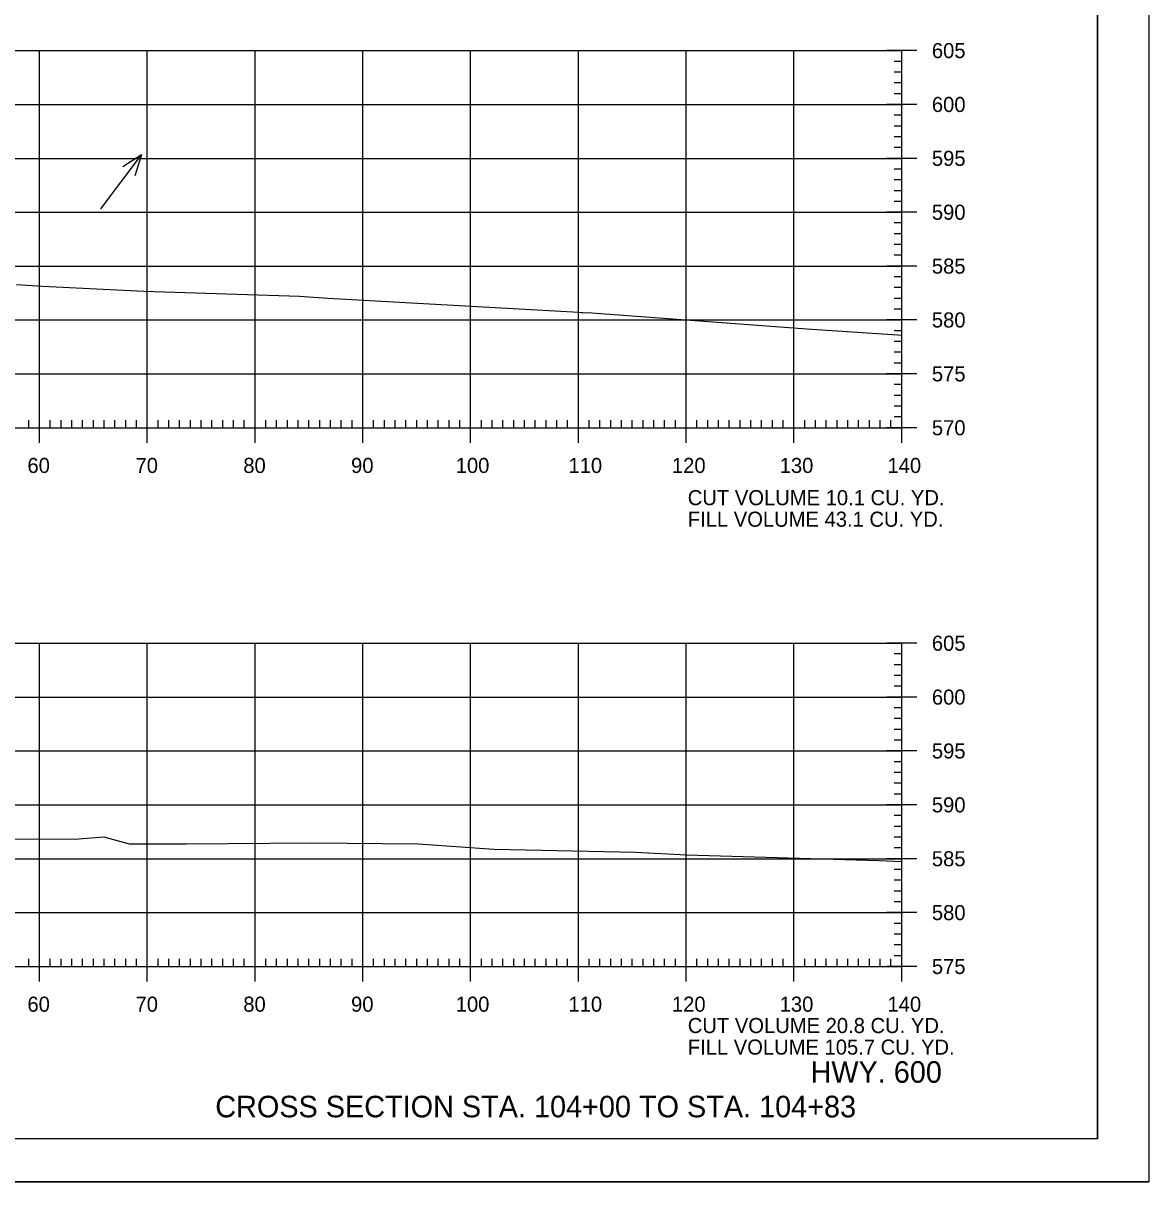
# Model space of a CAD drawing. Extents: x 961436 to 1372525, y 380079 to 2027791.
# Drawn here: x 1371253.4 to 1371357.8, y 380322.4 to 380429.9 of the extents above; entities that cross this region are included whole.
import ezdxf

# ---------------------------------------------------------------- set-up
doc = ezdxf.new("R2010")
doc.units = 0
for name, color, linetype in [('R_Axis', 7, 'Continuous'), ('R_Axis Annot', 7, 'Continuous'), ('R_Border', 7, 'Continuous'), ('R_Draft', 7, 'Continuous'), ('R_Exist Surface', 7, 'Continuous'), ('R_Grid', 7, 'Continuous'), ('R_No Plot', 7, 'Continuous'), ('R_Water Annot', 7, 'Continuous')]:
    doc.layers.add(name, color=color, linetype=linetype)

msp = doc.modelspace()

# ---------------------------------------------------------------- linework, layer by layer
at = {"layer": 'R_Axis'}
for p, q in [((1371336.28, 380427.4), (1371333.48, 380427.4)), ((1371334.88, 380392.4), (1371334.88, 380427.4)), ((1371334.88, 380426.4), (1371334.18, 380426.4)), ((1371334.88, 380425.4), (1371334.18, 380425.4)), ((1371334.88, 380424.4), (1371334.18, 380424.4)), ((1371334.88, 380423.4), (1371334.18, 380423.4)), ((1371336.28, 380422.4), (1371333.48, 380422.4)), ((1371334.88, 380421.4), (1371334.18, 380421.4)), ((1371334.88, 380420.4), (1371334.18, 380420.4)), ((1371334.88, 380419.4), (1371334.18, 380419.4)), ((1371334.88, 380418.4), (1371334.18, 380418.4)), ((1371336.28, 380417.4), (1371333.48, 380417.4)), ((1371334.88, 380416.4), (1371334.18, 380416.4)), ((1371334.88, 380415.4), (1371334.18, 380415.4)), ((1371334.88, 380414.4), (1371334.18, 380414.4)), ((1371334.88, 380413.4), (1371334.18, 380413.4)), ((1371336.28, 380412.4), (1371333.48, 380412.4)), ((1371334.88, 380411.4), (1371334.18, 380411.4)), ((1371334.88, 380410.4), (1371334.18, 380410.4)), ((1371334.88, 380409.4), (1371334.18, 380409.4)), ((1371334.88, 380408.4), (1371334.18, 380408.4)), ((1371336.28, 380407.4), (1371333.48, 380407.4)), ((1371334.88, 380406.4), (1371334.18, 380406.4)), ((1371334.88, 380405.4), (1371334.18, 380405.4)), ((1371334.88, 380404.4), (1371334.18, 380404.4)), ((1371336.28, 380402.4), (1371333.48, 380402.4)), ((1371334.88, 380403.4), (1371334.18, 380403.4)), ((1371334.88, 380401.4), (1371334.18, 380401.4)), ((1371334.88, 380400.4), (1371334.18, 380400.4)), ((1371334.88, 380399.4), (1371334.18, 380399.4)), ((1371334.88, 380398.4), (1371334.18, 380398.4)), ((1371336.28, 380397.4), (1371333.48, 380397.4)), ((1371334.88, 380396.4), (1371334.18, 380396.4)), ((1371334.88, 380395.4), (1371334.18, 380395.4)), ((1371254.88, 380391), (1371254.88, 380393.8)), ((1371264.88, 380391), (1371264.88, 380393.8)), ((1371274.88, 380391), (1371274.88, 380393.8)), ((1371284.88, 380391), (1371284.88, 380393.8)), ((1371294.88, 380391), (1371294.88, 380393.8)), ((1371304.88, 380391), (1371304.88, 380393.8)), ((1371314.88, 380391), (1371314.88, 380393.8)), ((1371324.88, 380391), (1371324.88, 380393.8)), ((1371334.88, 380394.4), (1371334.18, 380394.4)), ((1371334.88, 380391), (1371334.88, 380393.8)), ((1371253.88, 380392.4), (1371253.88, 380393.1)), ((1371255.88, 380392.4), (1371255.88, 380393.1)), ((1371256.88, 380392.4), (1371256.88, 380393.1)), ((1371257.88, 380392.4), (1371257.88, 380393.1)), ((1371258.88, 380392.4), (1371258.88, 380393.1)), ((1371259.88, 380392.4), (1371259.88, 380393.1)), ((1371260.88, 380392.4), (1371260.88, 380393.1)), ((1371261.88, 380392.4), (1371261.88, 380393.1)), ((1371262.88, 380392.4), (1371262.88, 380393.1)), ((1371263.88, 380392.4), (1371263.88, 380393.1)), ((1371265.88, 380392.4), (1371265.88, 380393.1)), ((1371266.88, 380392.4), (1371266.88, 380393.1)), ((1371267.88, 380392.4), (1371267.88, 380393.1)), ((1371268.88, 380392.4), (1371268.88, 380393.1)), ((1371269.88, 380392.4), (1371269.88, 380393.1)), ((1371270.88, 380392.4), (1371270.88, 380393.1)), ((1371271.88, 380392.4), (1371271.88, 380393.1)), ((1371272.88, 380392.4), (1371272.88, 380393.1)), ((1371273.88, 380392.4), (1371273.88, 380393.1)), ((1371275.88, 380392.4), (1371275.88, 380393.1)), ((1371276.88, 380392.4), (1371276.88, 380393.1)), ((1371277.88, 380392.4), (1371277.88, 380393.1)), ((1371278.88, 380392.4), (1371278.88, 380393.1)), ((1371279.88, 380392.4), (1371279.88, 380393.1)), ((1371280.88, 380392.4), (1371280.88, 380393.1)), ((1371281.88, 380392.4), (1371281.88, 380393.1)), ((1371282.88, 380392.4), (1371282.88, 380393.1)), ((1371283.88, 380392.4), (1371283.88, 380393.1)), ((1371285.88, 380392.4), (1371285.88, 380393.1)), ((1371286.88, 380392.4), (1371286.88, 380393.1)), ((1371287.88, 380392.4), (1371287.88, 380393.1)), ((1371288.88, 380392.4), (1371288.88, 380393.1)), ((1371289.88, 380392.4), (1371289.88, 380393.1)), ((1371290.88, 380392.4), (1371290.88, 380393.1)), ((1371291.88, 380392.4), (1371291.88, 380393.1)), ((1371292.88, 380392.4), (1371292.88, 380393.1)), ((1371293.88, 380392.4), (1371293.88, 380393.1)), ((1371295.88, 380392.4), (1371295.88, 380393.1)), ((1371296.88, 380392.4), (1371296.88, 380393.1)), ((1371297.88, 380392.4), (1371297.88, 380393.1)), ((1371298.88, 380392.4), (1371298.88, 380393.1)), ((1371299.88, 380392.4), (1371299.88, 380393.1)), ((1371300.88, 380392.4), (1371300.88, 380393.1)), ((1371301.88, 380392.4), (1371301.88, 380393.1)), ((1371302.88, 380392.4), (1371302.88, 380393.1)), ((1371303.88, 380392.4), (1371303.88, 380393.1)), ((1371305.88, 380392.4), (1371305.88, 380393.1)), ((1371306.88, 380392.4), (1371306.88, 380393.1)), ((1371307.88, 380392.4), (1371307.88, 380393.1)), ((1371308.88, 380392.4), (1371308.88, 380393.1)), ((1371309.88, 380392.4), (1371309.88, 380393.1)), ((1371310.88, 380392.4), (1371310.88, 380393.1)), ((1371311.88, 380392.4), (1371311.88, 380393.1)), ((1371312.88, 380392.4), (1371312.88, 380393.1)), ((1371313.88, 380392.4), (1371313.88, 380393.1)), ((1371315.88, 380392.4), (1371315.88, 380393.1)), ((1371316.88, 380392.4), (1371316.88, 380393.1)), ((1371317.88, 380392.4), (1371317.88, 380393.1)), ((1371318.88, 380392.4), (1371318.88, 380393.1)), ((1371319.88, 380392.4), (1371319.88, 380393.1)), ((1371320.88, 380392.4), (1371320.88, 380393.1)), ((1371321.88, 380392.4), (1371321.88, 380393.1)), ((1371322.88, 380392.4), (1371322.88, 380393.1)), ((1371323.88, 380392.4), (1371323.88, 380393.1)), ((1371325.88, 380392.4), (1371325.88, 380393.1)), ((1371326.88, 380392.4), (1371326.88, 380393.1)), ((1371327.88, 380392.4), (1371327.88, 380393.1)), ((1371328.88, 380392.4), (1371328.88, 380393.1)), ((1371329.88, 380392.4), (1371329.88, 380393.1)), ((1371330.88, 380392.4), (1371330.88, 380393.1)), ((1371331.88, 380392.4), (1371331.88, 380393.1)), ((1371332.88, 380392.4), (1371332.88, 380393.1)), ((1371333.88, 380392.4), (1371333.88, 380393.1)), ((1371334.88, 380393.4), (1371334.18, 380393.4)), ((1371054.88, 380392.4), (1371334.88, 380392.4)), ((1371336.28, 380392.4), (1371333.48, 380392.4)), ((1371336.28, 380372.4), (1371333.48, 380372.4)), ((1371334.88, 380342.4), (1371334.88, 380372.4)), ((1371334.88, 380371.4), (1371334.18, 380371.4)), ((1371334.88, 380370.4), (1371334.18, 380370.4)), ((1371334.88, 380369.4), (1371334.18, 380369.4)), ((1371334.88, 380368.4), (1371334.18, 380368.4)), ((1371336.28, 380367.4), (1371333.48, 380367.4)), ((1371334.88, 380366.4), (1371334.18, 380366.4)), ((1371334.88, 380365.4), (1371334.18, 380365.4)), ((1371334.88, 380364.4), (1371334.18, 380364.4)), ((1371334.88, 380363.4), (1371334.18, 380363.4)), ((1371336.28, 380362.4), (1371333.48, 380362.4)), ((1371334.88, 380361.4), (1371334.18, 380361.4)), ((1371334.88, 380360.4), (1371334.18, 380360.4)), ((1371334.88, 380359.4), (1371334.18, 380359.4)), ((1371334.88, 380358.4), (1371334.18, 380358.4)), ((1371336.28, 380357.4), (1371333.48, 380357.4)), ((1371334.88, 380356.4), (1371334.18, 380356.4)), ((1371334.88, 380355.4), (1371334.18, 380355.4)), ((1371334.88, 380354.4), (1371334.18, 380354.4)), ((1371334.88, 380353.4), (1371334.18, 380353.4)), ((1371336.28, 380352.4), (1371333.48, 380352.4)), ((1371334.88, 380351.4), (1371334.18, 380351.4)), ((1371334.88, 380350.4), (1371334.18, 380350.4)), ((1371334.88, 380349.4), (1371334.18, 380349.4)), ((1371334.88, 380348.4), (1371334.18, 380348.4)), ((1371336.28, 380347.4), (1371333.48, 380347.4)), ((1371334.88, 380346.4), (1371334.18, 380346.4)), ((1371334.88, 380345.4), (1371334.18, 380345.4)), ((1371334.88, 380344.4), (1371334.18, 380344.4)), ((1371254.88, 380341), (1371254.88, 380343.8)), ((1371264.88, 380341), (1371264.88, 380343.8)), ((1371274.88, 380341), (1371274.88, 380343.8)), ((1371284.88, 380341), (1371284.88, 380343.8)), ((1371294.88, 380341), (1371294.88, 380343.8)), ((1371304.88, 380341), (1371304.88, 380343.8)), ((1371314.88, 380341), (1371314.88, 380343.8)), ((1371324.88, 380341), (1371324.88, 380343.8)), ((1371334.88, 380343.4), (1371334.18, 380343.4)), ((1371334.88, 380341), (1371334.88, 380343.8)), ((1371054.88, 380342.4), (1371334.88, 380342.4)), ((1371253.88, 380342.4), (1371253.88, 380343.1)), ((1371255.88, 380342.4), (1371255.88, 380343.1)), ((1371256.88, 380342.4), (1371256.88, 380343.1)), ((1371257.88, 380342.4), (1371257.88, 380343.1)), ((1371258.88, 380342.4), (1371258.88, 380343.1)), ((1371259.88, 380342.4), (1371259.88, 380343.1)), ((1371260.88, 380342.4), (1371260.88, 380343.1)), ((1371261.88, 380342.4), (1371261.88, 380343.1)), ((1371262.88, 380342.4), (1371262.88, 380343.1)), ((1371263.88, 380342.4), (1371263.88, 380343.1)), ((1371265.88, 380342.4), (1371265.88, 380343.1)), ((1371266.88, 380342.4), (1371266.88, 380343.1)), ((1371267.88, 380342.4), (1371267.88, 380343.1)), ((1371268.88, 380342.4), (1371268.88, 380343.1)), ((1371269.88, 380342.4), (1371269.88, 380343.1)), ((1371270.88, 380342.4), (1371270.88, 380343.1)), ((1371271.88, 380342.4), (1371271.88, 380343.1)), ((1371272.88, 380342.4), (1371272.88, 380343.1)), ((1371273.88, 380342.4), (1371273.88, 380343.1)), ((1371275.88, 380342.4), (1371275.88, 380343.1)), ((1371276.88, 380342.4), (1371276.88, 380343.1)), ((1371277.88, 380342.4), (1371277.88, 380343.1)), ((1371278.88, 380342.4), (1371278.88, 380343.1)), ((1371279.88, 380342.4), (1371279.88, 380343.1)), ((1371280.88, 380342.4), (1371280.88, 380343.1)), ((1371281.88, 380342.4), (1371281.88, 380343.1)), ((1371282.88, 380342.4), (1371282.88, 380343.1)), ((1371283.88, 380342.4), (1371283.88, 380343.1)), ((1371285.88, 380342.4), (1371285.88, 380343.1)), ((1371286.88, 380342.4), (1371286.88, 380343.1)), ((1371287.88, 380342.4), (1371287.88, 380343.1)), ((1371288.88, 380342.4), (1371288.88, 380343.1)), ((1371289.88, 380342.4), (1371289.88, 380343.1)), ((1371290.88, 380342.4), (1371290.88, 380343.1)), ((1371291.88, 380342.4), (1371291.88, 380343.1)), ((1371292.88, 380342.4), (1371292.88, 380343.1)), ((1371293.88, 380342.4), (1371293.88, 380343.1)), ((1371295.88, 380342.4), (1371295.88, 380343.1)), ((1371296.88, 380342.4), (1371296.88, 380343.1)), ((1371297.88, 380342.4), (1371297.88, 380343.1)), ((1371298.88, 380342.4), (1371298.88, 380343.1)), ((1371299.88, 380342.4), (1371299.88, 380343.1)), ((1371300.88, 380342.4), (1371300.88, 380343.1)), ((1371301.88, 380342.4), (1371301.88, 380343.1)), ((1371302.88, 380342.4), (1371302.88, 380343.1)), ((1371303.88, 380342.4), (1371303.88, 380343.1)), ((1371305.88, 380342.4), (1371305.88, 380343.1)), ((1371306.88, 380342.4), (1371306.88, 380343.1)), ((1371307.88, 380342.4), (1371307.88, 380343.1)), ((1371308.88, 380342.4), (1371308.88, 380343.1)), ((1371309.88, 380342.4), (1371309.88, 380343.1)), ((1371310.88, 380342.4), (1371310.88, 380343.1)), ((1371311.88, 380342.4), (1371311.88, 380343.1)), ((1371312.88, 380342.4), (1371312.88, 380343.1)), ((1371313.88, 380342.4), (1371313.88, 380343.1)), ((1371315.88, 380342.4), (1371315.88, 380343.1)), ((1371316.88, 380342.4), (1371316.88, 380343.1)), ((1371317.88, 380342.4), (1371317.88, 380343.1)), ((1371318.88, 380342.4), (1371318.88, 380343.1)), ((1371319.88, 380342.4), (1371319.88, 380343.1)), ((1371320.88, 380342.4), (1371320.88, 380343.1)), ((1371321.88, 380342.4), (1371321.88, 380343.1)), ((1371322.88, 380342.4), (1371322.88, 380343.1)), ((1371323.88, 380342.4), (1371323.88, 380343.1)), ((1371325.88, 380342.4), (1371325.88, 380343.1)), ((1371326.88, 380342.4), (1371326.88, 380343.1)), ((1371327.88, 380342.4), (1371327.88, 380343.1)), ((1371328.88, 380342.4), (1371328.88, 380343.1)), ((1371329.88, 380342.4), (1371329.88, 380343.1)), ((1371330.88, 380342.4), (1371330.88, 380343.1)), ((1371331.88, 380342.4), (1371331.88, 380343.1)), ((1371332.88, 380342.4), (1371332.88, 380343.1)), ((1371336.28, 380342.4), (1371333.48, 380342.4)), ((1371333.88, 380342.4), (1371333.88, 380343.1))]:
    msp.add_line(p, q, dxfattribs=at)
at = {"layer": 'R_Border'}
for q in [(1371353.06, 380531.86), (1371036.88, 380326.4)]:
    msp.add_line((1371353.06, 380326.4), q, dxfattribs=at)
at = {"layer": 'R_Exist Surface'}
for points in [[(1371252.76, 380405.7), (1371255.15, 380405.54), (1371264.55, 380405.07), (1371279, 380404.62), (1371281.63, 380404.41), (1371304.92, 380403.11), (1371305.16, 380403.1), (1371305.29, 380403.09), (1371306.13, 380403.05), (1371326.08, 380401.59), (1371334.5, 380401.01), (1371334.88, 380400.98)], [(1371245, 380354.27), (1371258.13, 380354.22), (1371260.84, 380354.42), (1371263.19, 380353.78), (1371268.5, 380353.78), (1371280.11, 380353.86), (1371290, 380353.78), (1371297.05, 380353.28), (1371310.17, 380353.01), (1371314.92, 380352.77), (1371332.77, 380352.23), (1371334.88, 380352.15)]]:
    msp.add_lwpolyline(points, dxfattribs=at)
at = {"layer": 'R_Grid'}
for p, q in [((1371054.88, 380427.4), (1371334.88, 380427.4)), ((1371254.88, 380392.4), (1371254.88, 380427.4)), ((1371264.88, 380392.4), (1371264.88, 380427.4)), ((1371274.88, 380392.4), (1371274.88, 380427.4)), ((1371284.88, 380392.4), (1371284.88, 380427.4)), ((1371294.88, 380392.4), (1371294.88, 380427.4)), ((1371304.88, 380392.4), (1371304.88, 380427.4)), ((1371314.88, 380392.4), (1371314.88, 380427.4)), ((1371324.88, 380392.4), (1371324.88, 380427.4)), ((1371334.88, 380392.4), (1371334.88, 380427.4)), ((1371054.88, 380422.4), (1371334.88, 380422.4)), ((1371054.88, 380417.4), (1371334.88, 380417.4)), ((1371054.88, 380412.4), (1371334.88, 380412.4)), ((1371054.88, 380407.4), (1371334.88, 380407.4)), ((1371054.88, 380402.4), (1371334.88, 380402.4)), ((1371054.88, 380397.4), (1371334.88, 380397.4)), ((1371054.88, 380392.4), (1371334.88, 380392.4)), ((1371054.88, 380372.4), (1371334.88, 380372.4)), ((1371254.88, 380342.4), (1371254.88, 380372.4)), ((1371264.88, 380342.4), (1371264.88, 380372.4)), ((1371274.88, 380342.4), (1371274.88, 380372.4)), ((1371284.88, 380342.4), (1371284.88, 380372.4)), ((1371294.88, 380342.4), (1371294.88, 380372.4)), ((1371304.88, 380342.4), (1371304.88, 380372.4)), ((1371314.88, 380342.4), (1371314.88, 380372.4)), ((1371324.88, 380342.4), (1371324.88, 380372.4)), ((1371334.88, 380342.4), (1371334.88, 380372.4)), ((1371054.88, 380367.4), (1371334.88, 380367.4)), ((1371054.88, 380362.4), (1371334.88, 380362.4)), ((1371054.88, 380357.4), (1371334.88, 380357.4)), ((1371054.88, 380352.4), (1371334.88, 380352.4)), ((1371054.88, 380347.4), (1371334.88, 380347.4)), ((1371054.88, 380342.4), (1371334.88, 380342.4))]:
    msp.add_line(p, q, dxfattribs=at)
at = {"layer": 'R_No Plot'}
msp.add_line((1371024.48, 380322.42), (1371357.81, 380322.42), dxfattribs=at)
for points in [[(1371024.47, 380535.75), (1371357.81, 380535.75), (1371357.81, 380322.41), (1371024.47, 380322.41)], [(1371270.8, 380531.86), (1371290.42, 380531.86), (1371290.42, 380521.98), (1371306.53, 380521.98), (1371329.73, 380521.98), (1371329.85, 380493.82), (1371353.06, 380493.82), (1371353.06, 380326.4), (1371036.88, 380326.4), (1371036.88, 380531.86)]]:
    msp.add_lwpolyline(points, close=True, dxfattribs=at)
at = {"layer": 'R_Water Annot'}
for p, q in [((1371260.56, 380412.71), (1371264.34, 380417.73)), ((1371264.34, 380417.73), (1371262.62, 380416.61)), ((1371264.34, 380417.73), (1371263.74, 380415.77))]:
    msp.add_line(p, q, dxfattribs=at)

# ---------------------------------------------------------------- texts
at = {"layer": 'R_Axis Annot'}
for s, p in [('605', (1371337.68, 380426.7)), ('600', (1371337.68, 380421.7)), ('595', (1371337.68, 380416.7)), ('590', (1371337.68, 380411.7)), ('585', (1371337.68, 380406.7)), ('580', (1371337.68, 380401.7)), ('575', (1371337.68, 380396.7)), ('570', (1371337.68, 380391.7)), ('60', (1371253.76, 380388.2)), ('70', (1371263.79, 380388.2)), ('80', (1371273.79, 380388.2)), ('90', (1371283.79, 380388.2)), ('100', (1371293.5, 380388.2)), ('110', (1371303.96, 380388.2)), ('120', (1371313.56, 380388.2)), ('130', (1371323.56, 380388.2)), ('140', (1371333.56, 380388.2)), ('CUT VOLUME 10.1 CU. YD.', (1371315.03, 380385.21)), ('FILL VOLUME 43.1 CU. YD.', (1371315.03, 380383.21)), ('605', (1371337.68, 380371.7)), ('600', (1371337.68, 380366.7)), ('595', (1371337.68, 380361.7)), ('590', (1371337.68, 380356.7)), ('585', (1371337.68, 380351.7)), ('580', (1371337.68, 380346.7)), ('575', (1371337.68, 380341.7)), ('60', (1371253.76, 380338.2)), ('70', (1371263.79, 380338.2)), ('80', (1371273.79, 380338.2)), ('90', (1371283.79, 380338.2)), ('100', (1371293.5, 380338.2)), ('110', (1371303.96, 380338.2)), ('120', (1371313.56, 380338.2)), ('130', (1371323.56, 380338.2)), ('140', (1371333.56, 380338.2)), ('CUT VOLUME 20.8 CU. YD.', (1371315.03, 380336.22)), ('FILL VOLUME 105.7 CU. YD.', (1371315.03, 380334.22))]:
    msp.add_text(s, height=1.4, dxfattribs=at).set_placement(p)
at = {"layer": 'R_Draft'}
for s, p in [('HWY. 600', (1371326.42, 380331.61)), ('CROSS SECTION STA. 104+00 TO STA. 104+83', (1371271.19, 380328.4))]:
    msp.add_text(s, height=2, dxfattribs=at).set_placement(p)

doc.saveas('drawing.dxf')
